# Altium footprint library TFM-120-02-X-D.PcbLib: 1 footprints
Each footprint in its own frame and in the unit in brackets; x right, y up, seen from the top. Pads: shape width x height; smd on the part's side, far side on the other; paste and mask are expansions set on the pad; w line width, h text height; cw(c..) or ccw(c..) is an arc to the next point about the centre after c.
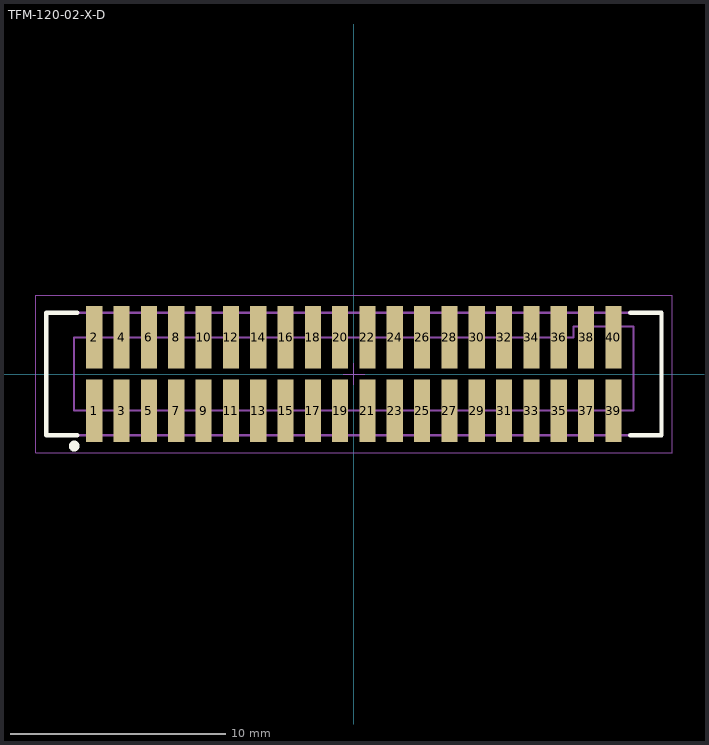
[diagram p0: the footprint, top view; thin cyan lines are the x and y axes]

## TFM-120-02-X-D [mm] "1.27mm pitch, 40 pin, micro terminal strip; double row, SMT"
height 2.21
pads (40):
  rect 0.75x2.9 smd mask+0: 1(-12.065,-1.714) 2(-12.065,1.714) 3(-10.795,-1.714) 4(-10.795,1.714) 5(-9.525,-1.714) 6(-9.525,1.714) 7(-8.255,-1.714) 8(-8.255,1.714) 9(-6.985,-1.714) 10(-6.985,1.714) 11(-5.715,-1.714) 12(-5.715,1.714) 13(-4.445,-1.714) 14(-4.445,1.714) 15(-3.175,-1.714) 16(-3.175,1.714) 17(-1.905,-1.714) 18(-1.905,1.714) 19(-0.635,-1.714) 20(-0.635,1.714) 21(0.635,-1.714) 22(0.635,1.714) 23(1.905,-1.714) 24(1.905,1.714) 25(3.175,-1.714) 26(3.175,1.714) 27(4.445,-1.714) 28(4.445,1.714) 29(5.715,-1.714) 30(5.715,1.714) 31(6.985,-1.714) 32(6.985,1.714) 33(8.255,-1.714) 34(8.255,1.714) 35(9.525,-1.714) 36(9.525,1.714) 37(10.795,-1.714) 38(10.795,1.714) 39(12.065,-1.714) 40(12.065,1.714)
Top Overlay:
  circle w0.25: c-13,-3.35 r0.125
  lines w0.2: -12.85,-2.85 -14.3,-2.85 -14.3,2.85 -12.85,2.85 ; 12.85,-2.85 14.3,-2.85 14.3,2.85 12.85,2.85
Mechanical 12:
  lines w0.001: -14.3,-2.85 14.3,-2.85 14.3,2.85 -14.3,2.85 -14.3,-2.85 ; -13.005,-1.702 13.005,-1.702 13.005,2.21 10.211,2.21 10.211,1.702 -13.005,1.702 -13.005,-1.702
Mechanical 13:
  circle w0.1: c-12.989,-3.356 r0.127
  lines w0.1: -14.3,-2.85 14.3,-2.85 14.3,2.85 -14.3,2.85 -14.3,-2.85 ; -13.005,-1.702 13.005,-1.702 13.005,2.21 10.211,2.21 10.211,1.702 -13.005,1.702 -13.005,-1.702
  text ".Designator" at 0,-0.127 h1.52
Mechanical 15:
  lines w0.05: -0.5,0 0.5,0 ; 0,-0.5 0,0.5 ; -14.783,-3.65 14.8,-3.65 14.8,3.65 -14.783,3.65 -14.783,-3.65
